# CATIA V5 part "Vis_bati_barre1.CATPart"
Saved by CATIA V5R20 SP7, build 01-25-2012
Part number: Vis_bati_barre1
Bounding box of the stored display mesh (mm): x -9 to 0.5, y 24.777 to 26.769, z 9.424 to 11.416
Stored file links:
  J:\IFMA\IAO\système avant mef\Vis_bati_barre1.CATPart
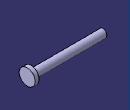
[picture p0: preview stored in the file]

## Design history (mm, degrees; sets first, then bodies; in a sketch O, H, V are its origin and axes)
Body1 (main body)
  Line1 "barre_1": stored without definition
  Point1 "Point.Eprim": stored without definition
  Plane1: type Normal, Curve Line1, RefPoint Point1
  DatumPoint1
  Line2 "axe_liaison_barre2_barre1": stored without definition
  Line3: stored without definition
  Line4 "axe_liaison_barre2_barre1": stored without definition
  Line5 "axe_pivot_bati_barre1": stored without definition
  Sketch1 on Plane1, origin (0, 25.7733, 0), H (-1, 0, 0), V (0, 0, 1)
    point P1 (9, 10.4199)
    line L1 (9, 10.4199) -> (9, 10.9199)
    line L2 (9, 10.9199) -> (0, 10.9199)
    point P3 (0, 10.9199)
    line L3 (0, 10.9199) -> (0, 11.4199)
    line L4 (0, 11.4199) -> (-0.5, 11.4199)
    line L5 (-0.5, 11.4199) -> (-0.5, 10.4199)
    point P6 (-0.5, 10.4199)
    reference projected point E1 (9, 10.4199) from vertex of DatumPoint1
    reference projected line E2 (0, 10.4199) -> (-20, 10.4199) from Line2
    reference projected line E3 (9, 10.4199) -> (2, 10.4199) from Line3
    reference projected line E4 (0, 10.4199) -> (-20, 10.4199) from Line4
    distance L2 E3 = 0.5
    distance E4 L4 = 1
    distance L5 L3 = 0.5
    vertical: L1 V, L3 V, L5 V
    coincidence: P3 V, P1 E1, P6 E2
    horizontal: L2 H, L4 H
  Shaft1: profile Sketch1, axis Line5, angle 360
